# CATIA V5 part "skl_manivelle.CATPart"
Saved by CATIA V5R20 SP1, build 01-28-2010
Part number: skl_manivelle
Publications: "PointA", "Plan_ref", "axe_ref", "Point_entraxe", "Plan_pivot_A", "Plan_pivot_entraxe", "axe_pivot_Pt_entraxe", "axe_pivot_A"
Bounding box of the stored display mesh (mm): x -40 to 40, y -50 to 0, z -220 to 0
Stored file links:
  C:\Users\Fabien-port\Desktop\test\skl_manivelle.CATPart
  C:\Users\Fabien-port\Desktop\test\ass_skl_mecanisme_a_coulisseau.CATProduct
  C:\Users\Fabien-port\Desktop\test\mecanisme_a_coulisseau.CATProduct
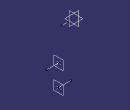
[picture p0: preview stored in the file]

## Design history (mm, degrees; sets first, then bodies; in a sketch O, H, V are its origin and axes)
External parameters (linked from other documents)
  External.entraxe_manivelle = 70 mm
Set1
  Point1 "PointA": linked copy from another document
  Plane1 "Plan_ref": linked copy from another document
  Line1 "axe_ref": linked copy from another document
Set2
  Point2 "Point_entraxe": (0, 0, 70 {= External.entraxe_manivelle}), relative to Point1
  Plane2 "Plan_pivot_A": type OffsetPt, RefPlane Plane1, RefPoint Point1
  Plane3 "Plan_pivot_entraxe": type OffsetPt, RefPlane Plane2, RefPoint Point2
  Line2 "axe_pivot_Pt_entraxe": type PtDir, RefPoint Point2, Direction Line1, Start 0, End 40
  Line3 "axe_pivot_A": type PtDir, RefPoint Point1, Direction Line1, Start 0, End 40
Body1 (main body)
